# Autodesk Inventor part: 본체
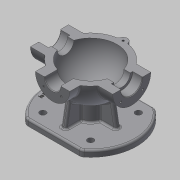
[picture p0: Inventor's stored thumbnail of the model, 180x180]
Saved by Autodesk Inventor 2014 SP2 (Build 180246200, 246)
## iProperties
Created: 2015-12
Part Number: 본체
Material: 일반
Document SubType Name: Modeling
Designer: mduedu
Density: 1 g/cm^3
Appearance: 기본값
Mass: 382.033 g
Surface Area: 843.851 cm^2
Volume: 382.033 cm^3
Author: mduedu
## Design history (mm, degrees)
sketch "스케치1"
  geometry: L1 (-53, 0)-(53, 0); A1 r 53 centre (0, 0) between (53, 0) and (-53, 0); 2 further points
  constraints: 2 coincident, 2 end point, 2 point on circle, 1 centre point, 1 horizontal, 1 midpoint
  dimensions: "d0" = 53 radius of A1
revolve "회전1" sketch "스케치1" stored, may be unused: angle "d2" = 90 deg
feature "쉘1" dims "d11" = 10
node "작업 평면1"
sketch "스케치2"
  geometry: C1 r 31 at (0, 0); 1 further point
  constraints: 1 centre point, 1 coincident
  dimensions: "d4" = 62 diameter of C1
extrude "돌출1" join sketch "스케치2" stored distance "d5" = 10; taper "d6" = 0 deg
node "작업 평면2"
sketch "스케치3"
  geometry: C1 r 28 at (0, 0); 1 further point
  constraints: 1 centre point, 1 coincident
  dimensions: "d8" = 56 diameter of C1
extrude "돌출2" join sketch "스케치3" stored distance "d9" = 10; taper "d10" = 0 deg
hole "구멍1" diameter "d14" = 35; stored, may be unused: countersink angle "d18" = 90 deg, drill point angle "d20" = 0 deg; dims "d12" = 10, "d13" = 10, "d15" = 6, "d16" = 4, "d17" = 2, "d19" = 16
hole "구멍2" diameter "d23" = 27; stored, may be unused: countersink angle "d27" = 90 deg, drill point angle "d29" = 0 deg; dims "d21" = 10, "d22" = 10, "d24" = 6, "d25" = 4, "d26" = 2, "d28" = 16
fillet "모깎기1" dims "d30" = 0.3
hole "구멍3" diameter "d33" = 26; stored, may be unused: countersink angle "d37" = 90 deg, drill point angle "d39" = 0 deg; dims "d31" = 10, "d32" = 10, "d34" = 6, "d35" = 4, "d36" = 2, "d38" = 16
chamfer "모따기1" distance "d40" = 1; stored, may be unused: second distance "d41" = 2, angle "d42" = 45 deg
sketch "스케치4"
  geometry: L1 (0, 0)-(0, -25); L2 (0, 0)-(-17.678, -17.678); A1 r 25 centre (0, 0) between (-17.678, -17.678) and (0, -25); 1 further point
  constraints: 4 end point, 2 point on circle, 1 centre point, 1 coincident, 1 vertical
  dimensions: "d43" = 50 diameter of A1; "d47" = 45 deg angle of L1 L2
hole "구멍4" sketch "스케치4" at (-17.678, -17.678) diameter "d49" = 3.242; stored, may be unused: countersink angle "d53" = 90 deg, drill point angle "d55" = 118 deg; dims "d50" = 11, "d51" = 4, "d52" = 2, "d54" = 13
sketch "스케치5"
  geometry: L1 (0, 0)-(0, -20); L2 (0, 0)-(-14.142, -14.142); A1 r 20 centre (0, 0) between (0, -20) and (-14.142, -14.142); 2 further points
  constraints: 4 end point, 2 coincident, 2 point on circle, 1 centre point, 1 vertical
  dimensions: "d59" = 40 diameter of A1; "d65" = 45 deg angle of L1 L2
hole "구멍5" sketch "스케치5" at (-14.142, -14.142) diameter "d67" = 3.242; stored, may be unused: countersink angle "d71" = 90 deg, drill point angle "d73" = 118 deg; dims "d68" = 8, "d69" = 4, "d70" = 2, "d72" = 10
node "작업 평면3"
sketch "스케치6"
  geometry: C1 r 75 at (0, 0); 1 further point
  constraints: 1 centre point, 1 coincident
  dimensions: "d78" = 150 diameter of C1
extrude "돌출3" join sketch "스케치6" distance "d80" = 10; taper "d81" = 0 deg
sketch "스케치7"
  geometry: C1 r 20 at (0, 0); 1 further point
  constraints: 1 centre point, 1 coincident
  dimensions: "d82" = 40 diameter of C1
extrude "돌출4" join sketch "스케치7" stored distance "d84" = 10; taper "d85" = 0 deg
sketch "스케치8"
  geometry: 2 further points
  constraints: 1 coincident
hole "구멍6" sketch "스케치8" at (0, 0) diameter "d86" = 20; stored, may be unused: countersink angle "d90" = 90 deg, drill point angle "d92" = 118 deg; dims "d87" = 7, "d88" = 40, "d89" = 5, "d91" = 10
fillet "모깎기2" dims "d93" = 0.3
sketch "스케치9"
  geometry: L1 (75, -75)-(-75, -75) reference; L2 (-45, -75)-(-38.245, -36.692); A1 r 53 centre (0, 0) between (42.988, 31) and (42.988, -31) reference; 1 further point
  constraints: 2 end point, 1 point on circle, 1 point on line
  dimensions: "d94" = 45 horizontal distance of L2.start point (0, 0); "d95" = 80 deg angle of L2 L1
feature "리브1" sketch "스케치9" dims "d96" = 1, "d97" = 8, "d98" = 0, "d99" = 0, "d100" = 1, "d101" = 1
sketch "스케치14"
  geometry: L1 (-45, 110)-(45, 110); L2 (45, 110)-(45, 60); L3 (45, 60)-(-45, 60); L4 (-45, 60)-(-45, 110); L5 (-45, 110)-(45, 60); L6 (45, 110)-(-45, 60); L7 (-75, 0)-(75, 0); L8 (-45, -110)-(45, -110); L9 (45, -110)-(45, -60); L10 (45, -60)-(-45, -60); L11 (-45, -60)-(-45, -110); L12 (-45, -110)-(45, -60); L13 (45, -110)-(-45, -60); A1 r 75 centre (0, 0) between (45, 60) and (-45, 60) reference; 4 further points
  constraints: 26 end point, 5 midpoint, 5 symmetric about line, 4 point on circle, 2 parallel, 2 perpendicular, 1 coincident, 1 horizontal
  dimensions: "d151" = 15 distance edge to line of A1 L3; "d152" = 50 distance of L3.end L1.start
extrude "돌출7" cut sketch "스케치14" stored distance "d153" = 0; taper "d154" = 0 deg
fillet "모깎기9" dims "d155" = 10
sketch "스케치10"
  geometry: L1 (0, 0)-(0, -55); L2 (0, 0)-(-38.891, -38.891); A1 r 55 centre (0, 0) between (0, -55) and (-38.891, -38.891); 2 further points
  constraints: 4 end point, 2 coincident, 2 point on circle, 1 centre point, 1 vertical
  dimensions: "d105" = 110 diameter of A1; "d107" = 45 deg angle of L1 L2
hole "구멍7" sketch "스케치10" at (-38.891, -38.891) diameter "d109" = 10; stored, may be unused: countersink angle "d113" = 90 deg, drill point angle "d115" = 118 deg; dims "d110" = 7, "d111" = 40, "d112" = 5, "d114" = 10
fillet "모깎기3" dims "d120" = 3
fillet "모깎기4" dims "d121" = 3, "d122" = 3
fillet "모깎기5" dims "d123" = 3
fillet "모깎기6" dims "d124" = 3
sketch "스케치11"
  geometry: 2 further points
  constraints: 1 vertical alignment, 1 other
  dimensions: "d157" = 63 distance of point (0, 63) point (0, 0)
feature "엠보싱1" sketch "스케치11" dims "d125" = 0.5, "d126" = 0
sketch "스케치12"
  geometry: L1 (0, 100)-(0, -100); L2 (0, 100)-(100, 100); L3 (100, 100)-(100, -100); L4 (100, -100)-(0, -100); 2 further points
  constraints: 8 end point, 3 perpendicular, 1 coincident, 1 midpoint, 1 vertical
  dimensions: "d127" = 200 distance of L2.end L3.end; "d129" = 100 distance between parallel lines of L1 L3
extrude "돌출5" cut sketch "스케치12" stored distance "d130" = 10; taper "d131" = 0 deg
sketch "스케치13"
  geometry: C1 r 7 at (0, 53); A1 r 53 centre (0, 0) between (42.113, 32.179) and (-42.113, 32.179) reference; 1 further point
  constraints: 1 centre point, 1 point on circle
  dimensions: "d132" = 14 diameter of C1
extrude "돌출6" join sketch "스케치13" distance "d134" = 15; taper "d135" = 0 deg; dims "d29" = 0
hole "구멍8" diameter "d139" = 3.242; stored, may be unused: countersink angle "d143" = 90 deg, drill point angle "d145" = 118 deg; dims "d140" = 8, "d141" = 4, "d142" = 2, "d144" = 10, "d148" = 10, "d149" = 10
fillet "모깎기7" dims "d146" = 3
fillet "모깎기8" dims "d147" = 3
node "솔리드1"
mirror "대칭1"
mirror "대칭2"
pattern_circular "원형 패턴1" dims angle "d57" = 360 deg
mirror "대칭3"
pattern_circular "원형 패턴2" dims angle "d75" = 360 deg
pattern_circular "원형 패턴3" dims angle "d103" = 360 deg
pattern_circular "원형 패턴4" dims angle "d118" = 360 deg
other parameters: "d3" = 67, "d7" = 62, "d77" = -85
